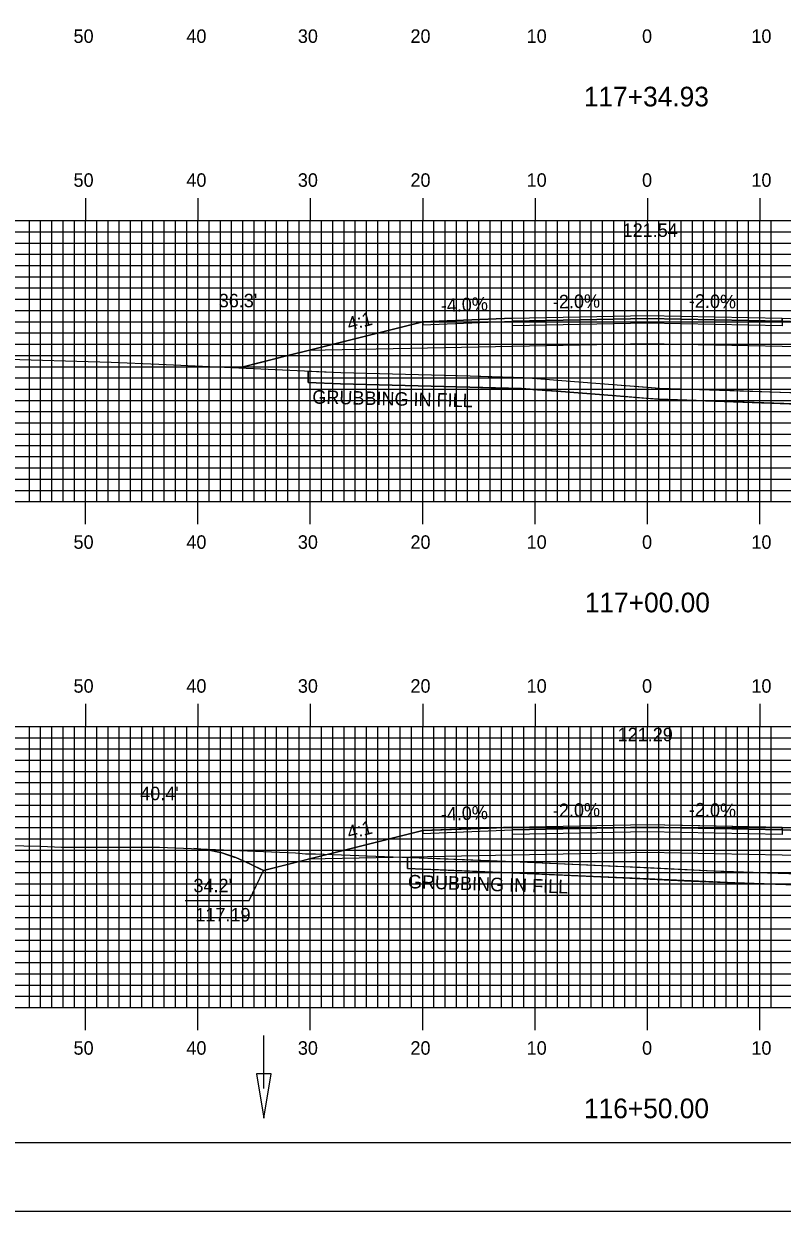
# Model space of a CAD drawing. Extents: x 1771235 to 1771579, y 442591 to 442811.
# Drawn here: x 1771345.6 to 1771413.1, y 442590.5 to 442696.2 of the extents above; entities that cross this region are included whole.
import ezdxf

# ---------------------------------------------------------------- set-up
doc = ezdxf.new("R2010")
doc.units = 0
for name, color, linetype in [('ANNOTATION', 7, 'Continuous'), ('BORDER', 7, 'Continuous'), ('D_Drainage_Ditch_Line', 7, 'Continuous'), ('D_Roadway_Centerline', 7, 'Continuous'), ('D_Roadway_Centerline_Text', 7, 'Continuous'), ('D_Roadway_Edge_Shoulder', 7, 'Continuous'), ('D_Roadway_Edge_TW', 7, 'Continuous'), ('D_Roadway_Pavement', 7, 'Continuous'), ('D_Roadway_SlopeLines', 7, 'Continuous'), ('D_Roadway_SubGrade', 7, 'Continuous'), ('D_Text_Standard', 7, 'Continuous'), ('GRUBBING IN FILL', 7, 'Continuous'), ('H_V ANNOTATION', 7, 'Continuous'), ('MAJOR', 7, 'Continuous'), ('MINOR', 7, 'Continuous'), ('PLOT BOUNDARY', 7, 'Continuous'), ('S_Roadway_Centerline', 7, 'Continuous')]:
    doc.layers.add(name, color=color, linetype=linetype)

msp = doc.modelspace()

# ---------------------------------------------------------------- linework, layer by layer
at = {"layer": 'ANNOTATION'}
msp.add_lwpolyline([(1771359.94, 442618.2), (1771365.63, 442618.2), (1771366.89, 442620.85)], dxfattribs=at)
at = {"layer": 'BORDER'}
msp.add_lwpolyline([(1771251.47, 442596.67), (1771571.47, 442596.67), (1771571.47, 442806.67), (1771251.47, 442806.67)], close=True, dxfattribs=at)
at = {"layer": 'D_Drainage_Ditch_Line'}
msp.add_line((1771366.93, 442601.47), (1771366.93, 442606.17), dxfattribs=at)
msp.add_lwpolyline([(1771367.58, 442602.78), (1771366.27, 442602.78), (1771366.93, 442598.84)], close=True, dxfattribs=at)
at = {"layer": 'D_Roadway_Centerline'}
for points in [[(1771364.74, 442665.56), (1771366.63, 442666.04), (1771369.07, 442666.65), (1771370.89, 442667.1), (1771381.07, 442669.65), (1771389.07, 442669.97), (1771401.07, 442670.21), (1771413.07, 442669.97), (1771421.07, 442669.65), (1771421.07, 442669.65), (1771431.24, 442667.1), (1771443.7, 442663.99), (1771448.11, 442662.89)], [(1771360.7, 442622.81), (1771361.71, 442622.71), (1771361.95, 442622.68), (1771363.2, 442622.42), (1771364.3, 442622.05), (1771364.45, 442622), (1771365.7, 442621.45), (1771366.52, 442621.04), (1771366.89, 442620.85), (1771370.89, 442621.85), (1771375.31, 442622.96), (1771381.07, 442624.4), (1771381.07, 442624.4), (1771386.21, 442624.6), (1771389.07, 442624.72), (1771401.07, 442624.96), (1771405.72, 442624.86), (1771413.05, 442624.72), (1771413.07, 442624.72), (1771419.18, 442624.47)]]:
    msp.add_lwpolyline(points, dxfattribs=at)
at = {"layer": 'D_Roadway_Edge_Shoulder'}
for points in [[(1771389.07, 442669.97), (1771381.07, 442669.65), (1771381.07, 442669.4), (1771389.07, 442669.72)], [(1771413.07, 442669.97), (1771421.07, 442669.65), (1771421.07, 442669.4), (1771413.07, 442669.72)], [(1771389.07, 442624.72), (1771381.07, 442624.4), (1771381.07, 442624.15), (1771389.07, 442624.47)], [(1771413.07, 442624.72), (1771421.07, 442624.4), (1771421.07, 442624.15), (1771413.07, 442624.47)]]:
    msp.add_lwpolyline(points, close=True, dxfattribs=at)
at = {"layer": 'D_Roadway_Edge_TW'}
for points in [[(1771389.07, 442669.72), (1771389.07, 442669.97), (1771401.07, 442670.21), (1771413.07, 442669.97), (1771413.07, 442669.72), (1771401.07, 442669.96)], [(1771389.07, 442624.47), (1771389.07, 442624.72), (1771401.07, 442624.96), (1771413.07, 442624.72), (1771413.07, 442624.47), (1771401.07, 442624.71)]]:
    msp.add_lwpolyline(points, close=True, dxfattribs=at)
at = {"layer": 'D_Roadway_Pavement'}
for points in [[(1771389.07, 442669.3), (1771389.07, 442669.72), (1771401.07, 442669.96), (1771413.07, 442669.72), (1771413.07, 442669.3), (1771401.07, 442669.54)], [(1771389.07, 442624.05), (1771389.07, 442624.47), (1771401.07, 442624.71), (1771413.07, 442624.47), (1771413.07, 442624.05), (1771401.07, 442624.29)]]:
    msp.add_lwpolyline(points, close=True, dxfattribs=at)
at = {"layer": 'D_Roadway_SlopeLines'}
for points in [[(1771381.07, 442669.65), (1771370.89, 442667.1), (1771369.07, 442666.65), (1771364.74, 442665.56)], [(1771381.07, 442624.4), (1771366.89, 442620.85)], [(1771366.89, 442620.85), (1771365.7, 442621.45), (1771364.45, 442622), (1771363.2, 442622.42), (1771361.95, 442622.68), (1771360.7, 442622.81)]]:
    msp.add_lwpolyline(points, dxfattribs=at)
at = {"layer": 'D_Roadway_SubGrade'}
for points in [[(1771389.07, 442667.47), (1771370.89, 442667.1), (1771381.07, 442669.65), (1771381.07, 442669.4), (1771389.07, 442669.72), (1771401.07, 442669.96), (1771413.07, 442669.72), (1771421.07, 442669.4), (1771421.07, 442669.65), (1771431.24, 442667.1), (1771413.07, 442667.47), (1771401.07, 442667.71)], [(1771389.07, 442622.22), (1771370.89, 442621.85), (1771381.07, 442624.4), (1771381.07, 442624.15), (1771389.07, 442624.47), (1771401.07, 442624.71), (1771413.07, 442624.47), (1771421.07, 442624.15), (1771421.07, 442624.4), (1771431.24, 442621.85), (1771413.07, 442622.22), (1771401.07, 442622.46)]]:
    msp.add_lwpolyline(points, close=True, dxfattribs=at)
at = {"layer": 'GRUBBING IN FILL'}
for p, q in [((1771370.89, 442665.27), (1771370.89, 442664.27)), ((1771370.89, 442665.27), (1771370.89, 442664.27)), ((1771379.72, 442622.03), (1771379.72, 442621.03)), ((1771379.72, 442622.03), (1771379.72, 442621.03))]:
    msp.add_line(p, q, dxfattribs=at)
for points in [[(1771370.89, 442665.27), (1771373.79, 442665.14), (1771379.53, 442664.99), (1771385.28, 442664.85), (1771387.69, 442664.78), (1771390.1, 442664.71), (1771391.97, 442664.57), (1771393.85, 442664.42), (1771398, 442664.09), (1771401.07, 442663.85), (1771401.07, 442662.85), (1771397.93, 442663.1), (1771393.77, 442663.42), (1771389.85, 442663.73), (1771385.25, 442663.85), (1771379.5, 442663.99), (1771373.75, 442664.14), (1771370.89, 442664.27)], [(1771370.89, 442665.27), (1771373.79, 442665.14), (1771379.53, 442664.99), (1771385.28, 442664.85), (1771387.69, 442664.78), (1771390.1, 442664.71), (1771391.97, 442664.57), (1771393.85, 442664.42), (1771398, 442664.09), (1771401.07, 442663.85), (1771401.07, 442662.85), (1771397.93, 442663.1), (1771393.77, 442663.42), (1771389.85, 442663.73), (1771385.25, 442663.85), (1771379.5, 442663.99), (1771373.75, 442664.14), (1771370.89, 442664.27)], [(1771401.07, 442663.85), (1771402.14, 442663.77), (1771407.95, 442663.57), (1771413.75, 442663.37), (1771424.61, 442663.13), (1771431.24, 442662.99), (1771431.24, 442661.99), (1771423.12, 442662.17), (1771414.99, 442662.34), (1771407.9, 442662.57), (1771402.09, 442662.77), (1771401.07, 442662.85)], [(1771401.07, 442663.85), (1771402.14, 442663.77), (1771407.95, 442663.57), (1771413.75, 442663.37), (1771424.61, 442663.13), (1771431.24, 442662.99), (1771431.24, 442661.99), (1771423.12, 442662.17), (1771414.99, 442662.34), (1771407.9, 442662.57), (1771402.09, 442662.77), (1771401.07, 442662.85)], [(1771379.72, 442621.03), (1771379.72, 442622.03), (1771388.45, 442621.69), (1771401.07, 442621.11), (1771401.07, 442620.11)], [(1771379.72, 442621.03), (1771379.72, 442622.03), (1771388.45, 442621.69), (1771401.07, 442621.11), (1771401.07, 442620.11)], [(1771401.07, 442621.11), (1771406.97, 442620.84), (1771418.4, 442620.44), (1771429.01, 442620.11), (1771431.24, 442619.97), (1771431.24, 442618.97), (1771427.87, 442619.13), (1771418.37, 442619.44), (1771408.86, 442619.75), (1771401.07, 442620.11)], [(1771401.07, 442621.11), (1771406.97, 442620.84), (1771418.4, 442620.44), (1771429.01, 442620.11), (1771431.24, 442619.97), (1771431.24, 442618.97), (1771427.87, 442619.13), (1771418.37, 442619.44), (1771408.86, 442619.75), (1771401.07, 442620.11)]]:
    msp.add_lwpolyline(points, close=True, dxfattribs=at)
for points in [[(1771370.89, 442664.27), (1771373.75, 442664.14), (1771385.25, 442663.85), (1771390.05, 442663.71), (1771393.77, 442663.42), (1771402.09, 442662.77), (1771413.72, 442662.37), (1771414.09, 442662.36), (1771414.99, 442662.34), (1771431.24, 442661.99)], [(1771370.89, 442664.27), (1771373.75, 442664.14), (1771385.25, 442663.85), (1771390.05, 442663.71), (1771393.77, 442663.42), (1771402.09, 442662.77), (1771413.72, 442662.37), (1771414.09, 442662.36), (1771414.99, 442662.34), (1771431.24, 442661.99)], [(1771379.72, 442621.03), (1771388.41, 442620.69), (1771398.87, 442620.21), (1771404.99, 442619.92), (1771408.86, 442619.75), (1771427.87, 442619.13), (1771428.96, 442619.11), (1771431.24, 442618.97)], [(1771379.72, 442621.03), (1771388.41, 442620.69), (1771398.87, 442620.21), (1771404.99, 442619.92), (1771408.86, 442619.75), (1771427.87, 442619.13), (1771428.96, 442619.11), (1771431.24, 442618.97)]]:
    msp.add_lwpolyline(points, dxfattribs=at)
at = {"layer": 'MAJOR'}
for p, q in [((1771351.07, 442680.67), (1771351.07, 442678.67)), ((1771361.07, 442680.67), (1771361.07, 442678.67)), ((1771371.07, 442680.67), (1771371.07, 442678.67)), ((1771381.07, 442680.67), (1771381.07, 442678.67)), ((1771391.07, 442680.67), (1771391.07, 442678.67)), ((1771401.07, 442680.67), (1771401.07, 442678.67)), ((1771411.07, 442680.67), (1771411.07, 442678.67)), ((1771261.07, 442678.67), (1771541.07, 442678.67)), ((1771261.07, 442678.67), (1771541.07, 442678.67)), ((1771351.07, 442653.67), (1771351.07, 442678.67)), ((1771361.07, 442653.67), (1771361.07, 442678.67)), ((1771371.07, 442653.67), (1771371.07, 442678.67)), ((1771381.07, 442653.67), (1771381.07, 442678.67)), ((1771391.07, 442653.67), (1771391.07, 442678.67)), ((1771401.07, 442653.67), (1771401.07, 442678.67)), ((1771411.07, 442653.67), (1771411.07, 442678.67)), ((1771261.07, 442673.67), (1771541.07, 442673.67)), ((1771261.07, 442668.67), (1771541.07, 442668.67)), ((1771261.07, 442663.67), (1771541.07, 442663.67)), ((1771261.07, 442658.67), (1771541.07, 442658.67)), ((1771261.07, 442653.67), (1771541.07, 442653.67)), ((1771261.07, 442653.67), (1771541.07, 442653.67)), ((1771351.07, 442651.66), (1771351.07, 442653.67)), ((1771361.07, 442651.66), (1771361.07, 442653.67)), ((1771371.07, 442651.66), (1771371.07, 442653.67)), ((1771381.07, 442651.66), (1771381.07, 442653.67)), ((1771391.07, 442651.66), (1771391.07, 442653.67)), ((1771401.07, 442651.66), (1771401.07, 442653.67)), ((1771411.07, 442651.66), (1771411.07, 442653.67)), ((1771351.07, 442635.67), (1771351.07, 442633.67)), ((1771361.07, 442635.67), (1771361.07, 442633.67)), ((1771371.07, 442635.67), (1771371.07, 442633.67)), ((1771381.07, 442635.67), (1771381.07, 442633.67)), ((1771391.07, 442635.67), (1771391.07, 442633.67)), ((1771401.07, 442635.67), (1771401.07, 442633.67)), ((1771411.07, 442635.67), (1771411.07, 442633.67)), ((1771261.07, 442633.67), (1771541.07, 442633.67)), ((1771261.07, 442633.67), (1771541.07, 442633.67)), ((1771351.07, 442608.67), (1771351.07, 442633.67)), ((1771361.07, 442608.67), (1771361.07, 442633.67)), ((1771371.07, 442608.67), (1771371.07, 442633.67)), ((1771381.07, 442608.67), (1771381.07, 442633.67)), ((1771391.07, 442608.67), (1771391.07, 442633.67)), ((1771401.07, 442608.67), (1771401.07, 442633.67)), ((1771411.07, 442608.67), (1771411.07, 442633.67)), ((1771261.07, 442628.67), (1771541.07, 442628.67)), ((1771261.07, 442623.67), (1771541.07, 442623.67)), ((1771261.07, 442618.67), (1771541.07, 442618.67)), ((1771261.07, 442613.67), (1771541.07, 442613.67)), ((1771261.07, 442608.67), (1771541.07, 442608.67)), ((1771261.07, 442608.67), (1771541.07, 442608.67)), ((1771351.07, 442606.66), (1771351.07, 442608.67)), ((1771361.07, 442606.66), (1771361.07, 442608.67)), ((1771371.07, 442606.66), (1771371.07, 442608.67)), ((1771381.07, 442606.66), (1771381.07, 442608.67)), ((1771391.07, 442606.66), (1771391.07, 442608.67)), ((1771401.07, 442606.66), (1771401.07, 442608.67)), ((1771411.07, 442606.66), (1771411.07, 442608.67))]:
    msp.add_line(p, q, dxfattribs=at)
at = {"layer": 'MINOR'}
for p, q in [((1771346.07, 442653.67), (1771346.07, 442678.67)), ((1771347.07, 442653.67), (1771347.07, 442678.67)), ((1771348.07, 442653.67), (1771348.07, 442678.67)), ((1771349.07, 442653.67), (1771349.07, 442678.67)), ((1771350.07, 442653.67), (1771350.07, 442678.67)), ((1771352.07, 442653.67), (1771352.07, 442678.67)), ((1771353.07, 442653.67), (1771353.07, 442678.67)), ((1771354.07, 442653.67), (1771354.07, 442678.67)), ((1771355.07, 442653.67), (1771355.07, 442678.67)), ((1771356.07, 442653.67), (1771356.07, 442678.67)), ((1771357.07, 442653.67), (1771357.07, 442678.67)), ((1771358.07, 442653.67), (1771358.07, 442678.67)), ((1771359.07, 442653.67), (1771359.07, 442678.67)), ((1771360.07, 442653.67), (1771360.07, 442678.67)), ((1771362.07, 442653.67), (1771362.07, 442678.67)), ((1771363.07, 442653.67), (1771363.07, 442678.67)), ((1771364.07, 442653.67), (1771364.07, 442678.67)), ((1771365.07, 442653.67), (1771365.07, 442678.67)), ((1771366.07, 442653.67), (1771366.07, 442678.67)), ((1771367.07, 442653.67), (1771367.07, 442678.67)), ((1771368.07, 442653.67), (1771368.07, 442678.67)), ((1771369.07, 442653.67), (1771369.07, 442678.67)), ((1771370.07, 442653.67), (1771370.07, 442678.67)), ((1771372.07, 442653.67), (1771372.07, 442678.67)), ((1771373.07, 442653.67), (1771373.07, 442678.67)), ((1771374.07, 442653.67), (1771374.07, 442678.67)), ((1771375.07, 442653.67), (1771375.07, 442678.67)), ((1771376.07, 442653.67), (1771376.07, 442678.67)), ((1771377.07, 442653.67), (1771377.07, 442678.67)), ((1771378.07, 442653.67), (1771378.07, 442678.67)), ((1771379.07, 442653.67), (1771379.07, 442678.67)), ((1771380.07, 442653.67), (1771380.07, 442678.67)), ((1771382.07, 442653.67), (1771382.07, 442678.67)), ((1771383.07, 442653.67), (1771383.07, 442678.67)), ((1771384.07, 442653.67), (1771384.07, 442678.67)), ((1771385.07, 442653.67), (1771385.07, 442678.67)), ((1771386.07, 442653.67), (1771386.07, 442678.67)), ((1771387.07, 442653.67), (1771387.07, 442678.67)), ((1771388.07, 442653.67), (1771388.07, 442678.67)), ((1771389.07, 442653.67), (1771389.07, 442678.67)), ((1771390.07, 442653.67), (1771390.07, 442678.67)), ((1771392.07, 442653.67), (1771392.07, 442678.67)), ((1771393.07, 442653.67), (1771393.07, 442678.67)), ((1771394.07, 442653.67), (1771394.07, 442678.67)), ((1771395.07, 442653.67), (1771395.07, 442678.67)), ((1771396.07, 442653.67), (1771396.07, 442678.67)), ((1771397.07, 442653.67), (1771397.07, 442678.67)), ((1771398.07, 442653.67), (1771398.07, 442678.67)), ((1771399.07, 442653.67), (1771399.07, 442678.67)), ((1771400.07, 442653.67), (1771400.07, 442678.67)), ((1771402.07, 442653.67), (1771402.07, 442678.67)), ((1771403.07, 442653.67), (1771403.07, 442678.67)), ((1771404.07, 442653.67), (1771404.07, 442678.67)), ((1771405.07, 442653.67), (1771405.07, 442678.67)), ((1771406.07, 442653.67), (1771406.07, 442678.67)), ((1771407.07, 442653.67), (1771407.07, 442678.67)), ((1771408.07, 442653.67), (1771408.07, 442678.67)), ((1771409.07, 442653.67), (1771409.07, 442678.67)), ((1771410.07, 442653.67), (1771410.07, 442678.67)), ((1771412.07, 442653.67), (1771412.07, 442678.67)), ((1771261.07, 442677.67), (1771541.07, 442677.67)), ((1771261.07, 442676.67), (1771541.07, 442676.67)), ((1771261.07, 442675.67), (1771541.07, 442675.67)), ((1771261.07, 442674.67), (1771541.07, 442674.67)), ((1771261.07, 442672.67), (1771541.07, 442672.67)), ((1771261.07, 442671.67), (1771541.07, 442671.67)), ((1771261.07, 442670.67), (1771541.07, 442670.67)), ((1771261.07, 442669.67), (1771541.07, 442669.67)), ((1771261.07, 442667.67), (1771541.07, 442667.67)), ((1771261.07, 442666.67), (1771541.07, 442666.67)), ((1771261.07, 442665.67), (1771541.07, 442665.67)), ((1771261.07, 442664.67), (1771541.07, 442664.67)), ((1771261.07, 442662.67), (1771541.07, 442662.67)), ((1771261.07, 442661.67), (1771541.07, 442661.67)), ((1771261.07, 442660.67), (1771541.07, 442660.67)), ((1771261.07, 442659.67), (1771541.07, 442659.67)), ((1771261.07, 442657.67), (1771541.07, 442657.67)), ((1771261.07, 442656.67), (1771541.07, 442656.67)), ((1771261.07, 442655.67), (1771541.07, 442655.67)), ((1771261.07, 442654.67), (1771541.07, 442654.67)), ((1771346.07, 442608.67), (1771346.07, 442633.67)), ((1771347.07, 442608.67), (1771347.07, 442633.67)), ((1771348.07, 442608.67), (1771348.07, 442633.67)), ((1771349.07, 442608.67), (1771349.07, 442633.67)), ((1771350.07, 442608.67), (1771350.07, 442633.67)), ((1771352.07, 442608.67), (1771352.07, 442633.67)), ((1771353.07, 442608.67), (1771353.07, 442633.67)), ((1771354.07, 442608.67), (1771354.07, 442633.67)), ((1771355.07, 442608.67), (1771355.07, 442633.67)), ((1771356.07, 442608.67), (1771356.07, 442633.67)), ((1771357.07, 442608.67), (1771357.07, 442633.67)), ((1771358.07, 442608.67), (1771358.07, 442633.67)), ((1771359.07, 442608.67), (1771359.07, 442633.67)), ((1771360.07, 442608.67), (1771360.07, 442633.67)), ((1771362.07, 442608.67), (1771362.07, 442633.67)), ((1771363.07, 442608.67), (1771363.07, 442633.67)), ((1771364.07, 442608.67), (1771364.07, 442633.67)), ((1771365.07, 442608.67), (1771365.07, 442633.67)), ((1771366.07, 442608.67), (1771366.07, 442633.67)), ((1771367.07, 442608.67), (1771367.07, 442633.67)), ((1771368.07, 442608.67), (1771368.07, 442633.67)), ((1771369.07, 442608.67), (1771369.07, 442633.67)), ((1771370.07, 442608.67), (1771370.07, 442633.67)), ((1771372.07, 442608.67), (1771372.07, 442633.67)), ((1771373.07, 442608.67), (1771373.07, 442633.67)), ((1771374.07, 442608.67), (1771374.07, 442633.67)), ((1771375.07, 442608.67), (1771375.07, 442633.67)), ((1771376.07, 442608.67), (1771376.07, 442633.67)), ((1771377.07, 442608.67), (1771377.07, 442633.67)), ((1771378.07, 442608.67), (1771378.07, 442633.67)), ((1771379.07, 442608.67), (1771379.07, 442633.67)), ((1771380.07, 442608.67), (1771380.07, 442633.67)), ((1771382.07, 442608.67), (1771382.07, 442633.67)), ((1771383.07, 442608.67), (1771383.07, 442633.67)), ((1771384.07, 442608.67), (1771384.07, 442633.67)), ((1771385.07, 442608.67), (1771385.07, 442633.67)), ((1771386.07, 442608.67), (1771386.07, 442633.67)), ((1771387.07, 442608.67), (1771387.07, 442633.67)), ((1771388.07, 442608.67), (1771388.07, 442633.67)), ((1771389.07, 442608.67), (1771389.07, 442633.67)), ((1771390.07, 442608.67), (1771390.07, 442633.67)), ((1771392.07, 442608.67), (1771392.07, 442633.67)), ((1771393.07, 442608.67), (1771393.07, 442633.67)), ((1771394.07, 442608.67), (1771394.07, 442633.67)), ((1771395.07, 442608.67), (1771395.07, 442633.67)), ((1771396.07, 442608.67), (1771396.07, 442633.67)), ((1771397.07, 442608.67), (1771397.07, 442633.67)), ((1771398.07, 442608.67), (1771398.07, 442633.67)), ((1771399.07, 442608.67), (1771399.07, 442633.67)), ((1771400.07, 442608.67), (1771400.07, 442633.67)), ((1771402.07, 442608.67), (1771402.07, 442633.67)), ((1771403.07, 442608.67), (1771403.07, 442633.67)), ((1771404.07, 442608.67), (1771404.07, 442633.67)), ((1771405.07, 442608.67), (1771405.07, 442633.67)), ((1771406.07, 442608.67), (1771406.07, 442633.67)), ((1771407.07, 442608.67), (1771407.07, 442633.67)), ((1771408.07, 442608.67), (1771408.07, 442633.67)), ((1771409.07, 442608.67), (1771409.07, 442633.67)), ((1771410.07, 442608.67), (1771410.07, 442633.67)), ((1771412.07, 442608.67), (1771412.07, 442633.67)), ((1771261.07, 442632.67), (1771541.07, 442632.67)), ((1771261.07, 442631.67), (1771541.07, 442631.67)), ((1771261.07, 442630.67), (1771541.07, 442630.67)), ((1771261.07, 442629.67), (1771541.07, 442629.67)), ((1771261.07, 442627.67), (1771541.07, 442627.67)), ((1771261.07, 442626.67), (1771541.07, 442626.67)), ((1771261.07, 442625.67), (1771541.07, 442625.67)), ((1771261.07, 442624.67), (1771541.07, 442624.67)), ((1771261.07, 442622.67), (1771541.07, 442622.67)), ((1771261.07, 442621.67), (1771541.07, 442621.67)), ((1771261.07, 442620.67), (1771541.07, 442620.67)), ((1771261.07, 442619.67), (1771541.07, 442619.67)), ((1771261.07, 442617.67), (1771541.07, 442617.67)), ((1771261.07, 442616.67), (1771541.07, 442616.67)), ((1771261.07, 442615.67), (1771541.07, 442615.67)), ((1771261.07, 442614.67), (1771541.07, 442614.67)), ((1771261.07, 442612.67), (1771541.07, 442612.67)), ((1771261.07, 442611.67), (1771541.07, 442611.67)), ((1771261.07, 442610.67), (1771541.07, 442610.67)), ((1771261.07, 442609.67), (1771541.07, 442609.67))]:
    msp.add_line(p, q, dxfattribs=at)
at = {"layer": 'PLOT BOUNDARY'}
msp.add_lwpolyline([(1771235.28, 442590.55), (1771575.28, 442590.55), (1771575.28, 442810.55), (1771235.28, 442810.55)], close=True, dxfattribs=at)
at = {"layer": 'S_Roadway_Centerline'}
for points in [[(1771343.15, 442666.38), (1771353.35, 442666.07), (1771357.59, 442665.9), (1771373.79, 442665.14), (1771385.28, 442664.85), (1771390.1, 442664.71), (1771393.85, 442664.42), (1771402.14, 442663.77), (1771413.75, 442663.37), (1771414.12, 442663.36), (1771415.01, 442663.34), (1771434.22, 442662.93), (1771437.6, 442662.9), (1771442.26, 442662.85), (1771449.06, 442662.89), (1771454.27, 442662.59), (1771461.08, 442662.17)], [(1771344.1, 442623.09), (1771347.05, 442623.02), (1771348.94, 442622.93), (1771357.66, 442622.94), (1771369.76, 442622.42), (1771370.64, 442622.35), (1771371.54, 442622.35), (1771388.45, 442621.69), (1771398.91, 442621.21), (1771405.03, 442620.92), (1771408.9, 442620.75), (1771427.9, 442620.13), (1771429.01, 442620.11), (1771439.68, 442619.44), (1771448.75, 442619.37), (1771452.32, 442619.47), (1771457.37, 442619.19)]]:
    msp.add_lwpolyline(points, dxfattribs=at)

# ---------------------------------------------------------------- texts
at = {"layer": 'ANNOTATION'}
for s, rotation, p in [('-4.0%', 2.2905, (1771382.7, 442670.51)), ('-2.0%', 1.1458, (1771392.67, 442670.84)), ('-2.0%', 358.8542, (1771404.75, 442670.93)), ('4:1', 14.0386, (1771374.52, 442668.87)), ('-2.0%', 1.1458, (1771392.67, 442625.59)), ('-2.0%', 358.8542, (1771404.75, 442625.68)), ('-4.0%', 2.2907, (1771382.7, 442625.26)), ('4:1', 14.039, (1771374.52, 442623.62))]:
    msp.add_text(s, height=1.2, rotation=rotation, dxfattribs=at).set_placement(p)
for s, p in [("34.2'", (1771360.67, 442618.92)), ('117.19', (1771360.84, 442616.32))]:
    msp.add_text(s, height=1.2, dxfattribs=at).set_placement(p)
at = {"layer": 'D_Roadway_Centerline'}
for s, p in [('C', (1771401.06, 442670.21)), ('L', (1771401.07, 442670.2)), ('C', (1771401.06, 442624.96)), ('L', (1771401.07, 442624.95))]:
    msp.add_text(s, height=0.0146, dxfattribs=at).set_placement(p)
at = {"layer": 'D_Roadway_Centerline_Text'}
for s, p in [('121.54', (1771398.86, 442677.21)), ('121.29', (1771398.42, 442632.35))]:
    msp.add_text(s, height=1.2, dxfattribs=at).set_placement(p)
at = {"layer": 'D_Text_Standard'}
for s, p in [("36.3'", (1771362.92, 442670.95)), ("40.4'", (1771355.93, 442627.11))]:
    msp.add_text(s, height=1.2, dxfattribs=at).set_placement(p)
at = {"layer": 'GRUBBING IN FILL'}
for rotation, p in [(358.649, (1771371.24, 442662.39)), (358.0947, (1771379.74, 442619.28))]:
    msp.add_text('GRUBBING IN FILL', height=1.2, rotation=rotation, dxfattribs=at).set_placement(p)
at = {"layer": 'H_V ANNOTATION'}
for s, height, p in [('50', 1.2, (1771350, 442694.47)), ('40', 1.2, (1771360.04, 442694.47)), ('30', 1.2, (1771369.96, 442694.47)), ('20', 1.2, (1771379.98, 442694.47)), ('10', 1.2, (1771390.32, 442694.47)), ('0', 1.2, (1771400.59, 442694.47)), ('10', 1.2, (1771410.32, 442694.47)), ('117+34.93', 1.75, (1771395.41, 442688.82)), ('50', 1.2, (1771350, 442681.67)), ('40', 1.2, (1771360.04, 442681.67)), ('30', 1.2, (1771369.96, 442681.67)), ('20', 1.2, (1771379.98, 442681.67)), ('10', 1.2, (1771390.32, 442681.67)), ('0', 1.2, (1771400.59, 442681.67)), ('10', 1.2, (1771410.32, 442681.67)), ('50', 1.2, (1771350, 442649.47)), ('40', 1.2, (1771360.04, 442649.47)), ('30', 1.2, (1771369.96, 442649.47)), ('20', 1.2, (1771379.98, 442649.47)), ('10', 1.2, (1771390.32, 442649.47)), ('0', 1.2, (1771400.59, 442649.47)), ('10', 1.2, (1771410.32, 442649.47)), ('117+00.00', 1.75, (1771395.5, 442643.82)), ('50', 1.2, (1771350, 442636.67)), ('40', 1.2, (1771360.04, 442636.67)), ('30', 1.2, (1771369.96, 442636.67)), ('20', 1.2, (1771379.98, 442636.67)), ('10', 1.2, (1771390.32, 442636.67)), ('0', 1.2, (1771400.59, 442636.67)), ('10', 1.2, (1771410.32, 442636.67)), ('50', 1.2, (1771350, 442604.47)), ('40', 1.2, (1771360.04, 442604.47)), ('30', 1.2, (1771369.96, 442604.47)), ('20', 1.2, (1771379.98, 442604.47)), ('10', 1.2, (1771390.32, 442604.47)), ('0', 1.2, (1771400.59, 442604.47)), ('10', 1.2, (1771410.32, 442604.47)), ('116+50.00', 1.75, (1771395.42, 442598.82))]:
    msp.add_text(s, height=height, dxfattribs=at).set_placement(p)

doc.saveas('drawing.dxf')
